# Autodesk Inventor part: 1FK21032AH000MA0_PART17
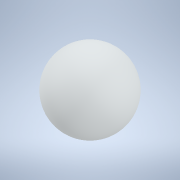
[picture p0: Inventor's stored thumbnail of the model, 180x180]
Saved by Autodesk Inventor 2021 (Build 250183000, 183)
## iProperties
Created: 2025-04
Part Number: 1FK21032AH000MA0_PART17
Material: Generic
Catalog Web Link: www.3dfindit.com
Description: -Servo synchronous motor
Document SubType Name: Modeling
Designer: psAdmin
Mass: 0.113097 g
Surface Area: 1.13097 cm^2
Volume: 0.113097 cm^3
Density: 1 g/cm^3
Appearance: PSOLRGB-212-217-219
Category: PARTsolutions
Title: 1FK21032AH000MA0_PART17
Author: Cadenas PARTsolutions
Comments: Servo synchronous motor
Sending System: PARTsolutions
Preprocessor: ST-DEVELOPER v19.3
PSOL_IDENT_0: {$CADENAS_DATA/23d-libs/siemens_ag/_cat_/45/10/1fk21032ah000ma0.prj},216 {VTYP=3D},{NB=1FK21032AH000
PSOL_IDENT_1: MA0_PART17},{LINA=1FK21032AH000MA0_PART17},{NN=1FK21032AH000MA0_PART17},{NOPRJ=TRUE},{DATE=19.08.202
PSOL_IDENT_2: 5 14:00:35},{GEOMDATE=30.07.2025 02:02:03},{VERSION=},{LINEID=10},{WBVAR=},{WBNUMERIC=}  {NB=1FK2103
PSOL_IDENT_3: 2AH000MA0_PART17},{LINA=1FK21032AH000MA0_PART17},{KT=DUMMY},{PREVIEW=../../../_pool_/14/8e/p_d211_xx
PSOL_IDENT_4: _00426j.png},{DESCSHORT=SIMOTICS S-1FK2 HD, SINAMICS S210 3AC 400V-480V, 0.59 Nm, 4500 rpm},{DESCLON
PSOL_IDENT_5: G=SIMOTICS S-1FK2 HD servo motor M0=0.64 Nm; PN = 0.28 kW at nN=4500 rpm (380-480 V); PN = 0.167 kW
PSOL_IDENT_6: at nN=2500 rpm (200-240 V); degree of protection IP64; cylindrical shaft D14 x 30 mm; absolute encod
PSOL_IDENT_7: er 22-bit + 12-bit multiturn (encoder AM22DQC); with OCC interface; plug size M17, rotatable; SIMOTI
PSOL_IDENT_8: CS S-1FK2 servomotorfor a wide range of uses in industrial environments. SIMOTICS S‑1FK2 servomotors
PSOL_IDENT_9: are compact synchronous motors with a high dynamic performance that set themselves apart as a resul
PSOL_IDENT_10: t of their high power density, degree of protection and overload capability. The motors are availabl
PSOL_IDENT_11: e in two variants: as High Dynamic variant (highest dynamic performance as a result of the low intri
PSOL_IDENT_12: nsic moment of inertia for applications demanding a high dynamic performance with low moved masses)
PSOL_IDENT_13: - and as Compact variant (precise and stable closed-loop control for medium up to large moved masses
PSOL_IDENT_14: as a result of a medium intrinsic moment of inertia). SIMOTICSS‑1FK2 servomotors fully exploit thei
PSOL_IDENT_15: r strengths in a system with the SINAMICSS210 frequency converter and simple connection using the on
PSOL_IDENT_16: e cable connection (OCC). Advantages include the short control and positioning times, fast and preci
PSOL_IDENT_17: se correction of disturbing quantities as well as stable control with a high dynamic performance. Th
PSOL_IDENT_18: e servo motors can be configured to address a wide range of requirements. For example with and witho
PSOL_IDENT_19: ut holding brake, IP64 or IP65 degree of protection, singleturn or multiturn absolute encoders - to
PSOL_IDENT_20: name just a few. Further, the servomotors are available in different shaft heights extending from 20
PSOL_IDENT_21: to 100. A shaft sealing ring is available to achieve an IP65 degree of protection and for subsequen
PSOL_IDENT_22: t mounting at the motor or as spare part. SIMOTICS - the optimum motor for each and every motion con
PSOL_IDENT_23: trol application.},{INTNO=195125335004},{SUPPLIERALTNO=1FK2103-2AH00-0MA0},{MANUID=1FK21032AH000MA0}
PSOL_IDENT_24: ,{MANUNAME=Siemens},{MANUTYPEDESC=SYNCHRONOUS MOTOR 1FK2 HD 0,64 NM},{AAU732=SIMOTICS},{AAO057=S-1FK
PSOL_IDENT_25: 2},{AAU734=SIMOTICS S-1FK2 HD servo motor M0=0.64 Nm; PN = 0.28 kW at nN=4500 rpm (380-480 V); PN =
PSOL_IDENT_26: 0.167 kW at nN=2500 rpm (200-240 V); degree of protection IP64; cylindrical shaft D14 x 30 mm; absol
PSOL_IDENT_27: ute encoder 22-bit + 12-bit multiturn (encoder AM22DQC); with OCC interface; plug size M17, rotatabl
PSOL_IDENT_28: e;},{AAW338=SYNCHRONOUS MOTOR 1FK2 HD 0,64 NM},{AAO742=SIMOTICS},{AAO663=4034106444624},{NOCUPEROU=1
PSOL_IDENT_29: },{PRICEQUANTITY=1},{QUANTITYMIN=1},{QUANTITYINT=1},{CTN=85015100},{COO=RO},{AAO676=1FK2103-2AH00-0M
PSOL_IDENT_30: A0},{AAO677=Siemens AG},{ORDERUNIT=C62},{CONTENTUNIT=C62}
NB: 1FK21032AH000MA0_PART17
NT: Servo synchronous motor
NBSYN: $MANUID._PART17
LINA: 1FK21032AH000MA0_PART17
CATALOG: SIEMENS
PREVIEW: ../../../_pool_/14/8e/p_d211_xx_00426j.png
DESCSHORT: SIMOTICS S-1FK2 HD, SINAMICS S210 3AC 400V-480V, 0.59 Nm, 4500 rpm
DESCLONG: SIMOTICS S-1FK2 HD servo motor M0=0.64 Nm; PN = 0.28 kW at nN=4500 rpm (380-480 V); PN = 0.167 kW at nN=2500 rpm (200-240 V); degree of protection IP64; cylindr
INTNO: 195125335004
SUPPLIERALTNO: 1FK2103-2AH00-0MA0
MANUID: 1FK21032AH000MA0
MANUNAME: Siemens
MANUTYPEDESC: SYNCHRONOUS MOTOR 1FK2 HD 0,64 NM
AAU732: SIMOTICS
AAO057: S-1FK2
AAU734: SIMOTICS S-1FK2 HD servo motor M0=0.64 Nm; PN = 0.28 kW at nN=4500 rpm (380-480 V); PN = 0.167 kW at nN=2500 rpm (200-240 V); degree of protection IP64; cylindr
AAW338: SYNCHRONOUS MOTOR 1FK2 HD 0,64 NM
AAO742: SIMOTICS
AAO663: 4034106444624.0
NOCUPEROU: 1
PRICEQUANTITY: 1
QUANTITYMIN: 1
QUANTITYINT: 1
CTN: 85015100
COO: RO
ARTICLENO: 1FK21032AH000MA0_PART17
BOMINFO: 1FK21032AH000MA0_PART17
CREATOR: CADENAS GmbH
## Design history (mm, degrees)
feature "2025_04_17_15_00_20_0760"
body "Solid1"
